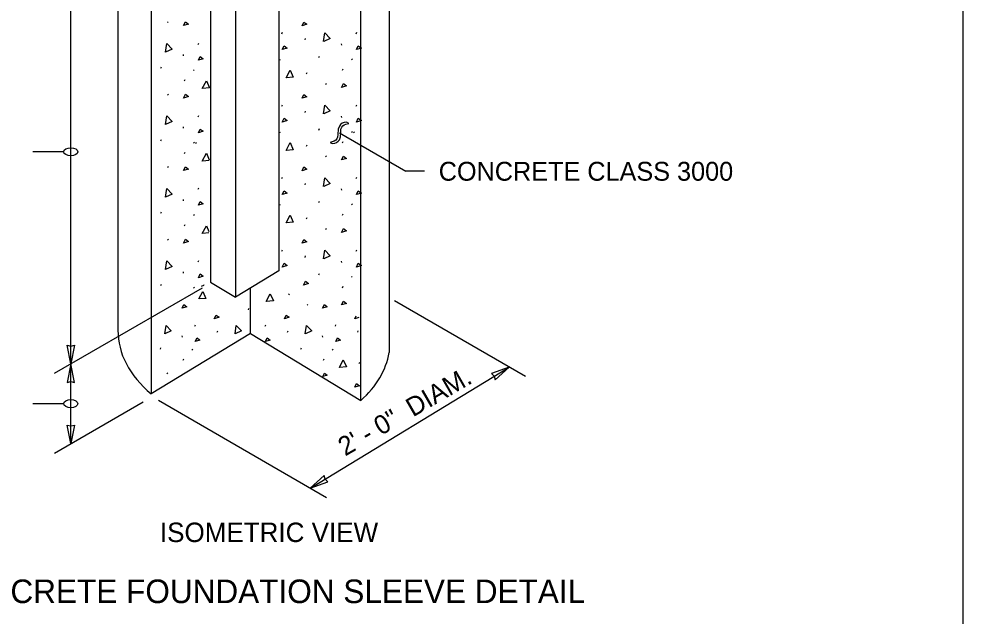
# Model space of a CAD drawing. Extents: x 99862 to 103151, y 100000 to 108076.
# Drawn here: x 102350 to 103151, y 107058 to 107564 of the extents above; entities that cross this region are included whole.
import ezdxf

# ---------------------------------------------------------------- set-up
doc = ezdxf.new("R2010")
doc.units = 0
for name, color, linetype in [('Level 1', 7, 'Continuous'), ('Level 15', 7, 'Continuous'), ('Level 20', 7, 'Continuous'), ('Level 6', 7, 'Continuous')]:
    doc.layers.add(name, color=color, linetype=linetype)

msp = doc.modelspace()

# ---------------------------------------------------------------- linework, layer by layer
at = {"layer": 'Level 1'}
msp.add_lwpolyline([(99862, 105999.5), (103151, 105999.5), (103151, 108075.5), (99862, 108075.5)], close=True, dxfattribs=at)
at = {"layer": 'Level 15'}
for p, q in [((102394.27, 107271.94), (102394.27, 107631.6)), ((102621.1, 107470.92), (102620.73, 107466.52)), ((102622.03, 107473.47), (102621.1, 107470.92)), ((102623.1, 107474.87), (102622.03, 107473.47)), ((102624.47, 107475.89), (102623.1, 107474.87)), ((102623.18, 107468.37), (102623.41, 107470.92)), ((102623.41, 107470.92), (102624.04, 107472.73)), ((102624.04, 107472.73), (102624.86, 107473.78)), ((102626.15, 107476.52), (102624.47, 107475.89)), ((102624.86, 107473.78), (102625.96, 107474.58)), ((102625.96, 107474.58), (102627.58, 107475.2)), ((102628.12, 107476.78), (102626.15, 107476.52)), ((102627.58, 107475.2), (102629.95, 107475.72)), ((102629.95, 107475.72), (102628.12, 107476.78)), ((102619.99, 107462.7), (102619.07, 107461.62)), ((102620.52, 107464.11), (102619.99, 107462.7)), ((102620.73, 107466.52), (102620.52, 107464.11)), ((102622, 107467.72), (102678.29, 107435.22)), ((102622.02, 107461.99), (102622.92, 107464.29)), ((102622.92, 107464.29), (102623.18, 107468.37)), ((102617.68, 107460.75), (102614.11, 107459.76)), ((102614.11, 107459.76), (102615.94, 107458.71)), ((102615.94, 107458.71), (102618.06, 107459.07)), ((102619.07, 107461.62), (102617.68, 107460.75)), ((102618.06, 107459.07), (102619.72, 107459.71)), ((102619.72, 107459.71), (102621.02, 107460.67)), ((102621.02, 107460.67), (102622.02, 107461.99)), ((102388.27, 107451.77), (102362.13, 107451.77)), ((102694.29, 107435.22), (102678.29, 107435.22)), ((102394.27, 107204.36), (102394.27, 107271.94)), ((102597.86, 107166.89), (102766.08, 107269.24)), ((102388.27, 107238.15), (102362.13, 107238.15))]:
    msp.add_line(p, q, dxfattribs=at)
for points in [[(102380.47, 107263.97), (102506.07, 107336.49)], [(102779.94, 107261.24), (102668.75, 107325.43)], [(102380.41, 107196.36), (102455.62, 107239.78)], [(102611.11, 107158.52), (102468.53, 107240.83)]]:
    msp.add_lwpolyline(points, dxfattribs=at)
for points in [[(102394.27, 107271.94), (102391.19, 107287.67), (102394.27, 107286.94), (102397.35, 107287.67)], [(102394.27, 107271.94), (102391.19, 107256.22), (102394.27, 107256.95), (102397.35, 107256.22)], [(102766.08, 107269.24), (102751.05, 107263.7), (102753.27, 107261.44), (102754.25, 107258.43)], [(102394.27, 107204.36), (102391.19, 107220.08), (102394.27, 107219.35), (102397.35, 107220.08)], [(102597.25, 107166.52), (102612.29, 107172.06), (102610.06, 107174.31), (102609.08, 107177.32)]]:
    msp.add_lwpolyline(points, close=True, dxfattribs=at)
for centre in [(102394.27, 107451.77), (102394.27, 107238.15)]:
    msp.add_ellipse(centre, major_axis=(-6, 0), ratio=0.57735, dxfattribs=at)
at = {"layer": 'Level 6'}
for p, q in [((102533.88, 107749.22), (102533.88, 107328.38)), ((102434.27, 107727.11), (102434.27, 107300.6)), ((102570.82, 107714.75), (102570.82, 107350.85)), ((102512.63, 107702), (102512.63, 107341.31)), ((102462.36, 107671.42), (102462.36, 107246.49)), ((102640.19, 107240.99), (102640.19, 107672.55)), ((102664.18, 107613.92), (102664.18, 107281.49)), ((102476.31, 107562.04), (102476.83, 107561.26)), ((102573.31, 107551.88), (102573.83, 107553.04)), ((102636.29, 107551.88), (102636.8, 107553.04)), ((102502.28, 107542.82), (102502.8, 107543.98)), ((102592.91, 107546.6), (102593.43, 107547.76)), ((102623.57, 107543.36), (102623.7, 107542.2)), ((102489.56, 107534.3), (102489.69, 107533.14)), ((102571.12, 107530.14), (102571.64, 107529.36)), ((102604.65, 107531.64), (102605.16, 107532.8)), ((102632.37, 107530.43), (102632.88, 107529.66)), ((102470.64, 107522.58), (102471.15, 107523.74)), ((102498.36, 107521.37), (102498.88, 107520.6)), ((102594.2, 107517.91), (102594.72, 107519.07)), ((102624.76, 107520.87), (102625.28, 107522.03)), ((102490.75, 107511.81), (102491.27, 107512.97)), ((102610.32, 107509.65), (102610.83, 107508.88)), ((102476.31, 107500.59), (102476.83, 107499.82)), ((102573.31, 107490.44), (102573.83, 107491.6)), ((102592.91, 107485.16), (102593.43, 107486.32)), ((102636.29, 107490.44), (102636.8, 107491.6)), ((102502.28, 107481.38), (102502.8, 107482.54)), ((102623.57, 107481.92), (102623.7, 107480.76)), ((102489.56, 107472.86), (102489.69, 107471.7)), ((102604.65, 107470.2), (102605.16, 107471.36)), ((102470.64, 107461.14), (102471.15, 107462.3)), ((102571.12, 107468.69), (102571.64, 107467.92)), ((102632.37, 107468.99), (102632.88, 107468.21)), ((102634.09, 107468.69), (102634.61, 107467.92)), ((102498.36, 107459.93), (102498.88, 107459.16)), ((102500.09, 107459.64), (102500.6, 107458.86)), ((102594.2, 107456.47), (102594.72, 107457.63)), ((102624.76, 107459.43), (102625.28, 107460.59)), ((102490.75, 107450.37), (102491.27, 107451.53)), ((102610.32, 107448.21), (102610.83, 107447.44)), ((102476.31, 107439.15), (102476.83, 107438.38)), ((102573.31, 107429), (102573.83, 107430.16)), ((102636.29, 107429), (102636.8, 107430.16)), ((102592.91, 107423.71), (102593.43, 107424.87)), ((102502.28, 107419.94), (102502.8, 107421.1)), ((102623.57, 107420.48), (102623.7, 107419.32)), ((102489.56, 107411.42), (102489.69, 107410.26)), ((102571.12, 107407.25), (102571.64, 107406.48)), ((102604.65, 107408.76), (102605.16, 107409.92)), ((102632.37, 107407.55), (102632.88, 107406.77)), ((102470.64, 107399.7), (102471.15, 107400.86)), ((102498.36, 107398.49), (102498.88, 107397.71)), ((102624.76, 107397.99), (102625.28, 107399.15)), ((102490.75, 107388.93), (102491.27, 107390.09)), ((102594.2, 107395.02), (102594.72, 107396.18)), ((102610.32, 107386.77), (102610.83, 107386)), ((102476.31, 107377.71), (102476.83, 107376.94)), ((102573.31, 107367.56), (102573.83, 107368.72)), ((102636.29, 107367.56), (102636.8, 107368.72)), ((102502.28, 107358.5), (102502.8, 107359.66)), ((102592.91, 107362.27), (102593.43, 107363.43)), ((102623.57, 107359.03), (102623.7, 107357.87)), ((102489.56, 107349.97), (102489.69, 107348.81)), ((102570.82, 107350.85), (102533.88, 107328.38)), ((102604.65, 107347.32), (102605.16, 107348.48)), ((102632.37, 107346.11), (102632.88, 107345.33)), ((102470.64, 107338.26), (102471.15, 107339.42)), ((102498.36, 107337.05), (102498.88, 107336.27)), ((102512.63, 107341.31), (102533.88, 107328.38)), ((102546.75, 107297.84), (102546.75, 107336.17)), ((102624.76, 107336.55), (102625.28, 107337.71)), ((102579.25, 107330.35), (102579.75, 107331.46)), ((102544.87, 107317.82), (102545.38, 107318.98)), ((102594.79, 107322.39), (102595.29, 107321.64)), ((102499.56, 107303.87), (102500.05, 107304.98)), ((102559.11, 107303.87), (102559.61, 107304.98)), ((102618.66, 107303.87), (102619.16, 107304.98)), ((102546.75, 107297.84), (102462.36, 107246.49)), ((102488.46, 107295.65), (102488.58, 107294.53)), ((102518.45, 107298.77), (102518.95, 107299.89)), ((102546.75, 107297.84), (102640.19, 107240.99)), ((102578.01, 107298.77), (102578.5, 107299.89)), ((102607.56, 107295.65), (102607.69, 107294.53)), ((102637.56, 107298.77), (102638.06, 107299.89)), ((102470.21, 107284.35), (102470.71, 107285.47)), ((102496.94, 107284.35), (102497.44, 107283.6)), ((102589.32, 107284.35), (102589.82, 107285.47)), ((102616.05, 107284.35), (102616.55, 107283.6)), ((102489.61, 107275.13), (102490.11, 107276.25)), ((102608.71, 107275.13), (102609.21, 107276.25)), ((102638.8, 107272.27), (102639.3, 107273.39)), ((102475.68, 107264.32), (102476.18, 107263.57))]:
    msp.add_line(p, q, dxfattribs=at)
for points in [[(102489.85, 107558.68), (102491.4, 107561.91), (102493.98, 107559.97), (102489.85, 107558.68)], [(102590.36, 107558.53), (102591.91, 107561.75), (102594.48, 107559.82), (102590.36, 107558.53)], [(102608.6, 107545.26), (102609.62, 107552.63), (102614.24, 107547.86), (102608.72, 107545.31)], [(102474.59, 107536.2), (102475.61, 107543.57), (102480.23, 107538.8), (102474.71, 107536.25)], [(102573.57, 107538.34), (102575.12, 107541.57), (102577.7, 107539.63), (102573.57, 107538.34)], [(102636.55, 107538.34), (102638.09, 107541.57), (102640.67, 107539.63), (102636.55, 107538.34)], [(102502.54, 107529.29), (102504.09, 107532.51), (102506.66, 107530.57), (102502.54, 107529.29)], [(102576.79, 107514.43), (102580.28, 107521), (102582.98, 107514.94), (102576.92, 107514.43)], [(102505.76, 107505.37), (102509.24, 107511.94), (102511.9, 107506)], [(102511.9, 107505.88), (102505.89, 107505.37)], [(102623.86, 107506.3), (102625.4, 107509.53), (102627.98, 107507.59), (102623.86, 107506.3)], [(102489.85, 107497.24), (102491.4, 107500.47), (102493.98, 107498.53), (102489.85, 107497.24)], [(102590.36, 107497.08), (102591.91, 107500.31), (102594.48, 107498.37), (102590.36, 107497.08)], [(102608.6, 107483.82), (102609.62, 107491.19), (102614.24, 107486.42), (102608.72, 107483.87)], [(102474.59, 107474.76), (102475.61, 107482.13), (102480.23, 107477.36), (102474.71, 107474.81)], [(102573.57, 107476.9), (102575.12, 107480.13), (102577.7, 107478.19), (102573.57, 107476.9)], [(102636.55, 107476.9), (102638.09, 107480.13), (102640.67, 107478.19), (102636.55, 107476.9)], [(102502.54, 107467.84), (102504.09, 107471.07), (102506.66, 107469.13), (102502.54, 107467.84)], [(102576.79, 107452.98), (102580.28, 107459.56), (102582.98, 107453.5), (102576.92, 107452.98)], [(102505.76, 107443.92), (102509.24, 107450.5), (102511.67, 107445.06)], [(102623.86, 107444.86), (102625.4, 107448.08), (102627.98, 107446.15), (102623.86, 107444.86)], [(102489.85, 107435.8), (102491.4, 107439.02), (102493.98, 107437.09), (102489.85, 107435.8)], [(102511.67, 107444.42), (102505.89, 107443.92)], [(102590.36, 107435.64), (102591.91, 107438.87), (102594.48, 107436.93), (102590.36, 107435.64)], [(102608.6, 107422.38), (102609.62, 107429.75), (102614.24, 107424.98), (102608.72, 107422.42)], [(102474.59, 107413.32), (102475.61, 107420.69), (102480.23, 107415.92), (102474.71, 107413.36)], [(102573.57, 107415.46), (102575.12, 107418.69), (102577.7, 107416.75), (102573.57, 107415.46)], [(102636.55, 107415.46), (102638.09, 107418.69), (102640.67, 107416.75), (102636.55, 107415.46)], [(102502.54, 107406.4), (102504.09, 107409.63), (102506.66, 107407.69), (102502.54, 107406.4)], [(102576.79, 107391.54), (102580.28, 107398.12), (102582.98, 107392.06), (102576.92, 107391.54)], [(102505.76, 107382.48), (102509.24, 107389.06), (102511.45, 107384.13)], [(102511.44, 107382.96), (102505.89, 107382.48)], [(102623.86, 107383.42), (102625.4, 107386.64), (102627.98, 107384.71), (102623.86, 107383.42)], [(102489.85, 107374.36), (102491.4, 107377.58), (102493.98, 107375.65), (102489.85, 107374.36)], [(102590.36, 107374.2), (102591.91, 107377.43), (102594.48, 107375.49), (102590.36, 107374.2)], [(102608.6, 107360.94), (102609.62, 107368.31), (102614.24, 107363.54), (102608.72, 107360.98)], [(102474.59, 107351.88), (102475.61, 107359.25), (102480.23, 107354.48), (102474.71, 107351.92)], [(102573.57, 107354.02), (102575.12, 107357.24), (102577.7, 107355.31), (102573.57, 107354.02)], [(102636.55, 107354.02), (102638.09, 107357.24), (102640.67, 107355.31), (102636.55, 107354.02)], [(102502.54, 107344.96), (102504.09, 107348.19), (102506.66, 107346.25), (102502.54, 107344.96)], [(102591.73, 107338.74), (102593.28, 107341.97), (102595.86, 107340.03), (102591.73, 107338.74)], [(102506.98, 107338.89), (102506.7, 107338.52), (102504.93, 107337.64)], [(102502.91, 107326.99), (102506.27, 107333.33), (102508.88, 107327.49), (102503.04, 107326.99)], [(102559.88, 107324.88), (102563.36, 107331.45), (102566.07, 107325.39), (102560.01, 107324.88)], [(102488.74, 107319.16), (102490.23, 107322.27), (102492.72, 107320.4), (102488.74, 107319.16)], [(102607.84, 107319.16), (102609.33, 107322.27), (102611.82, 107320.4), (102607.84, 107319.16)], [(102623.86, 107321.98), (102625.4, 107325.2), (102627.98, 107323.27), (102623.86, 107321.98)], [(102515.99, 107310.27), (102517.48, 107313.38), (102519.97, 107311.51), (102515.99, 107310.27)], [(102575.54, 107310.27), (102577.04, 107313.38), (102579.52, 107311.51), (102575.54, 107310.27)], [(102635.1, 107310.27), (102636.24, 107312.65)], [(102638.51, 107311.34), (102635.1, 107310.27)], [(102474.03, 107297.48), (102475.01, 107304.59), (102479.46, 107299.99), (102474.14, 107297.52)], [(102533.58, 107297.48), (102534.56, 107304.59), (102539.02, 107299.99), (102533.69, 107297.52)], [(102593.13, 107297.48), (102594.12, 107304.59), (102598.57, 107299.99), (102593.25, 107297.52)], [(102499.8, 107290.81), (102501.3, 107293.92), (102503.78, 107292.05), (102499.8, 107290.81)], [(102559.37, 107290.83), (102560.85, 107293.92), (102563.34, 107292.05), (102559.39, 107290.82)], [(102618.91, 107290.81), (102620.4, 107293.92), (102622.89, 107292.05), (102618.91, 107290.81)], [(102622.02, 107268.92), (102625.37, 107275.26), (102627.99, 107269.41), (102622.14, 107268.92)], [(102607.91, 107261.23), (102609.33, 107264.19), (102611.82, 107262.33), (102608.05, 107261.15)], [(102635.1, 107252.2), (102636.59, 107255.3), (102639.07, 107253.44), (102635.1, 107252.2)]]:
    msp.add_lwpolyline(points, dxfattribs=at)
for centre, major_axis, ratio, start_param, end_param in [((102549.57, 107297.7), (115.26, -4.48), 0.700961, 3.161089, 3.882262), ((102549.56, 107292.82), (115.3, -4.48), 0.700713, 5.643435, 6.19809)]:
    msp.add_ellipse(centre, major_axis=major_axis, ratio=ratio, start_param=start_param, end_param=end_param, dxfattribs=at)

# ---------------------------------------------------------------- texts
at = {"layer": 'Level 20'}
for s, height, rotation, p in [('CONCRETE CLASS 3000', 16, 360, (102706.29, 107427.22)), ('2\' - 0"  DIAM.', 16, 29.99868, (102626.92, 107193.34)), ('ISOMETRIC VIEW', 16.5, 360, (102469.82, 107120.88)), ('CONCRETE FOUNDATION SLEEVE DETAIL', 20, 360, (102283.63, 107069.13))]:
    msp.add_text(s, height=height, rotation=rotation, dxfattribs=at).set_placement(p)

doc.saveas('drawing.dxf')
